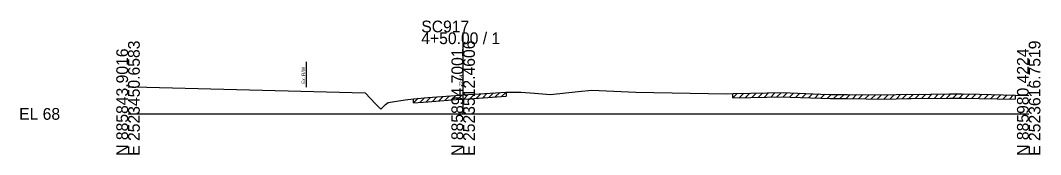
# Model space of a CAD drawing. Extents: x -26 to 218, y -10 to 12021.
# Drawn here: x -25.7 to 217.8, y 4490.3 to 4522.3 of the extents above; entities that cross this region are included whole.
import ezdxf

# ---------------------------------------------------------------- set-up
doc = ezdxf.new("R2010")
doc.units = 0
for name, color, linetype in [('RD_GPK_XS_Cell', 7, 'Continuous'), ('RD_XS_ExGround', 7, 'Continuous'), ('RD_XS_ExPaveRet', 7, 'Continuous'), ('RD_XS_ExRW', 7, 'Continuous'), ('RD_XS_TX_Elev_EX', 7, 'Continuous')]:
    doc.layers.add(name, color=color, linetype=linetype)

msp = doc.modelspace()

# ---------------------------------------------------------------- linework, layer by layer
at = {"layer": 'RD_GPK_XS_Cell'}
for p, q in [((80, 4500), (80, 4519.44)), ((0, 4500), (80, 4500)), ((80, 4500), (215, 4500))]:
    msp.add_line(p, q, dxfattribs=at)
at = {"layer": 'RD_XS_ExGround'}
for p, q in [((0, 4506.48), (0.7, 4506.47)), ((0.7, 4506.47), (1.39, 4506.45)), ((1.39, 4506.45), (56.57, 4505.01)), ((107.45, 4505.32), (110.72, 4505.64)), ((110.72, 4505.64), (121.19, 4505.17)), ((56.57, 4505.01), (59.06, 4502.42)), ((62.07, 4502.74), (66.16, 4503.35)), ((66.16, 4503.35), (68.16, 4503.63)), ((68.16, 4503.63), (71.53, 4503.9)), ((71.53, 4503.9), (79.26, 4504.49)), ((79.26, 4504.49), (80, 4504.54)), ((80, 4504.54), (82.57, 4504.71)), ((82.57, 4504.71), (90.23, 4505.21)), ((90.23, 4505.21), (93.86, 4505.15)), ((93.86, 4505.15), (97.01, 4504.95)), ((97.01, 4504.95), (100.82, 4504.65)), ((100.82, 4504.65), (107.45, 4505.32)), ((121.19, 4505.17), (142.83, 4504.78)), ((142.83, 4504.78), (144.41, 4504.83)), ((144.41, 4504.83), (148.63, 4504.92)), ((148.63, 4504.92), (156.36, 4505.07)), ((156.36, 4505.07), (158.08, 4505.02)), ((158.08, 4505.02), (165.34, 4504.73)), ((165.34, 4504.73), (167.65, 4504.64)), ((167.65, 4504.64), (171.73, 4504.64)), ((171.73, 4504.64), (180.66, 4504.53)), ((180.66, 4504.53), (186.08, 4504.68)), ((186.08, 4504.68), (186.96, 4504.66)), ((186.96, 4504.66), (196.06, 4504.75)), ((196.06, 4504.75), (199.01, 4504.77)), ((199.01, 4504.77), (203.15, 4504.69)), ((203.15, 4504.69), (211.77, 4504.5)), ((211.77, 4504.5), (215, 4504.35)), ((59.06, 4502.42), (60.37, 4501.17)), ((60.37, 4501.17), (61.48, 4502.22)), ((61.48, 4502.22), (62.07, 4502.74))]:
    msp.add_line(p, q, dxfattribs=at)
at = {"layer": 'RD_XS_ExPaveRet'}
for p, q in [((68.16, 4502.63), (69.25, 4503.72)), ((68.16, 4502.63), (68.16, 4503.63)), ((69.66, 4502.75), (70.75, 4503.84)), ((71.16, 4502.87), (72.24, 4503.95)), ((71.53, 4502.9), (79.26, 4503.49)), ((72.66, 4502.99), (73.74, 4504.07)), ((74.16, 4503.1), (75.24, 4504.18)), ((75.66, 4503.22), (76.74, 4504.3)), ((77.16, 4503.33), (78.24, 4504.41)), ((78.66, 4503.44), (79.74, 4504.52)), ((79.26, 4503.49), (80, 4503.54)), ((80, 4503.54), (82.57, 4503.71)), ((80.16, 4503.55), (81.23, 4504.62)), ((81.66, 4503.65), (82.73, 4504.72)), ((82.57, 4503.71), (90.23, 4504.21)), ((83.16, 4503.74), (84.23, 4504.81)), ((84.66, 4503.84), (85.73, 4504.91)), ((86.16, 4503.94), (87.23, 4505.01)), ((87.66, 4504.04), (88.73, 4505.11)), ((89.16, 4504.14), (90.23, 4505.21)), ((90.23, 4505.21), (90.23, 4504.21)), ((144.41, 4503.83), (145.43, 4504.85)), ((144.41, 4503.83), (144.41, 4504.83)), ((144.41, 4503.83), (148.63, 4503.92)), ((145.91, 4503.86), (146.93, 4504.88)), ((147.41, 4503.89), (148.43, 4504.92)), ((148.63, 4503.92), (156.36, 4504.07)), ((148.91, 4503.93), (149.92, 4504.95)), ((150.41, 4503.95), (151.42, 4504.97)), ((151.91, 4503.98), (152.92, 4505)), ((153.41, 4504.01), (154.42, 4505.03)), ((154.91, 4504.04), (155.92, 4505.06)), ((156.36, 4504.07), (158.08, 4504.02)), ((156.41, 4504.07), (157.37, 4505.04)), ((157.91, 4504.02), (158.87, 4504.98)), ((158.08, 4504.02), (165.34, 4503.73)), ((159.41, 4503.96), (160.37, 4504.92)), ((160.91, 4503.9), (161.87, 4504.87)), ((162.41, 4503.84), (163.37, 4504.81)), ((163.91, 4503.79), (164.87, 4504.75)), ((165.34, 4503.73), (167.65, 4503.64)), ((165.41, 4503.73), (166.37, 4504.69)), ((166.91, 4503.67), (167.88, 4504.64)), ((167.65, 4503.64), (171.73, 4503.64)), ((168.41, 4503.64), (169.41, 4504.64)), ((169.91, 4503.64), (170.91, 4504.64)), ((171.41, 4503.64), (172.4, 4504.63)), ((171.73, 4503.64), (180.66, 4503.53)), ((172.91, 4503.63), (173.89, 4504.62)), ((174.41, 4503.61), (175.39, 4504.6)), ((175.91, 4503.59), (176.89, 4504.58)), ((177.41, 4503.57), (178.39, 4504.56)), ((178.91, 4503.56), (179.89, 4504.54)), ((180.41, 4503.54), (181.42, 4504.56)), ((180.66, 4503.53), (186.08, 4503.68)), ((181.91, 4503.57), (182.93, 4504.6)), ((183.41, 4503.61), (184.43, 4504.64)), ((184.91, 4503.65), (185.93, 4504.68)), ((186.08, 4503.68), (186.96, 4503.66)), ((186.41, 4503.68), (187.39, 4504.66)), ((186.96, 4503.66), (196.06, 4503.75)), ((187.91, 4503.67), (188.91, 4504.68)), ((189.41, 4503.68), (190.41, 4504.69)), ((190.91, 4503.7), (191.91, 4504.71)), ((192.41, 4503.71), (193.41, 4504.72)), ((193.91, 4503.73), (194.91, 4504.74)), ((195.41, 4503.74), (196.41, 4504.75)), ((196.06, 4503.75), (199.01, 4503.77)), ((196.91, 4503.75), (197.92, 4504.76)), ((198.41, 4503.77), (199.4, 4504.77)), ((199.01, 4503.77), (203.15, 4503.69)), ((199.91, 4503.76), (200.88, 4504.73)), ((201.41, 4503.72), (202.38, 4504.7)), ((202.91, 4503.69), (203.88, 4504.67)), ((203.15, 4503.69), (211.77, 4503.5)), ((204.41, 4503.66), (205.38, 4504.64)), ((205.91, 4503.63), (206.88, 4504.6)), ((207.41, 4503.59), (208.38, 4504.57)), ((208.91, 4503.56), (209.88, 4504.54)), ((210.41, 4503.53), (211.38, 4504.51)), ((211.77, 4504.5), (211.77, 4503.5)), ((68.16, 4502.63), (71.53, 4502.9))]:
    msp.add_line(p, q, dxfattribs=at)
at = {"layer": 'RD_XS_ExRW'}
msp.add_line((42.5, 4512.38), (42.5, 4506.38), dxfattribs=at)

# ---------------------------------------------------------------- texts
at = {"layer": 'RD_GPK_XS_Cell'}
for s, p in [('SC917', (70, 4519.44)), ('4+50.00 / 1', (70, 4516.64)), ('EL 68', (-26, 4498.6))]:
    msp.add_text(s, height=2.8, dxfattribs=at).set_placement(p)
for s, p in [('N 885843.9016', (0, 4490)), ('E 2523450.6583', (2.8, 4490)), ('N 885894.7001', (80, 4490)), ('E 2523512.4606', (82.8, 4490)), ('N 885980.4224', (215, 4490)), ('E 2523616.7519', (217.8, 4490))]:
    msp.add_text(s, height=2.8, rotation=90, dxfattribs=at).set_placement(p)
at = {"layer": 'RD_XS_ExRW'}
msp.add_text('Ex. R/W ', height=0.8, rotation=90, dxfattribs=at).set_placement((42.25, 4507.16))
at = {"layer": 'RD_XS_TX_Elev_EX'}
msp.add_text('72.54', height=0.8, rotation=90, dxfattribs=at).set_placement((79.9, 4506.54))

doc.saveas('drawing.dxf')
